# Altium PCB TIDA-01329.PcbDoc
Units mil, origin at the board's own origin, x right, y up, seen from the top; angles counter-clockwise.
Board outline 2100 x 1960 mil, 2 copper layers (Top Layer, Bottom Layer), stack 62 mil thick; 51 components, 43 nets, 188 pads, 34 vias.
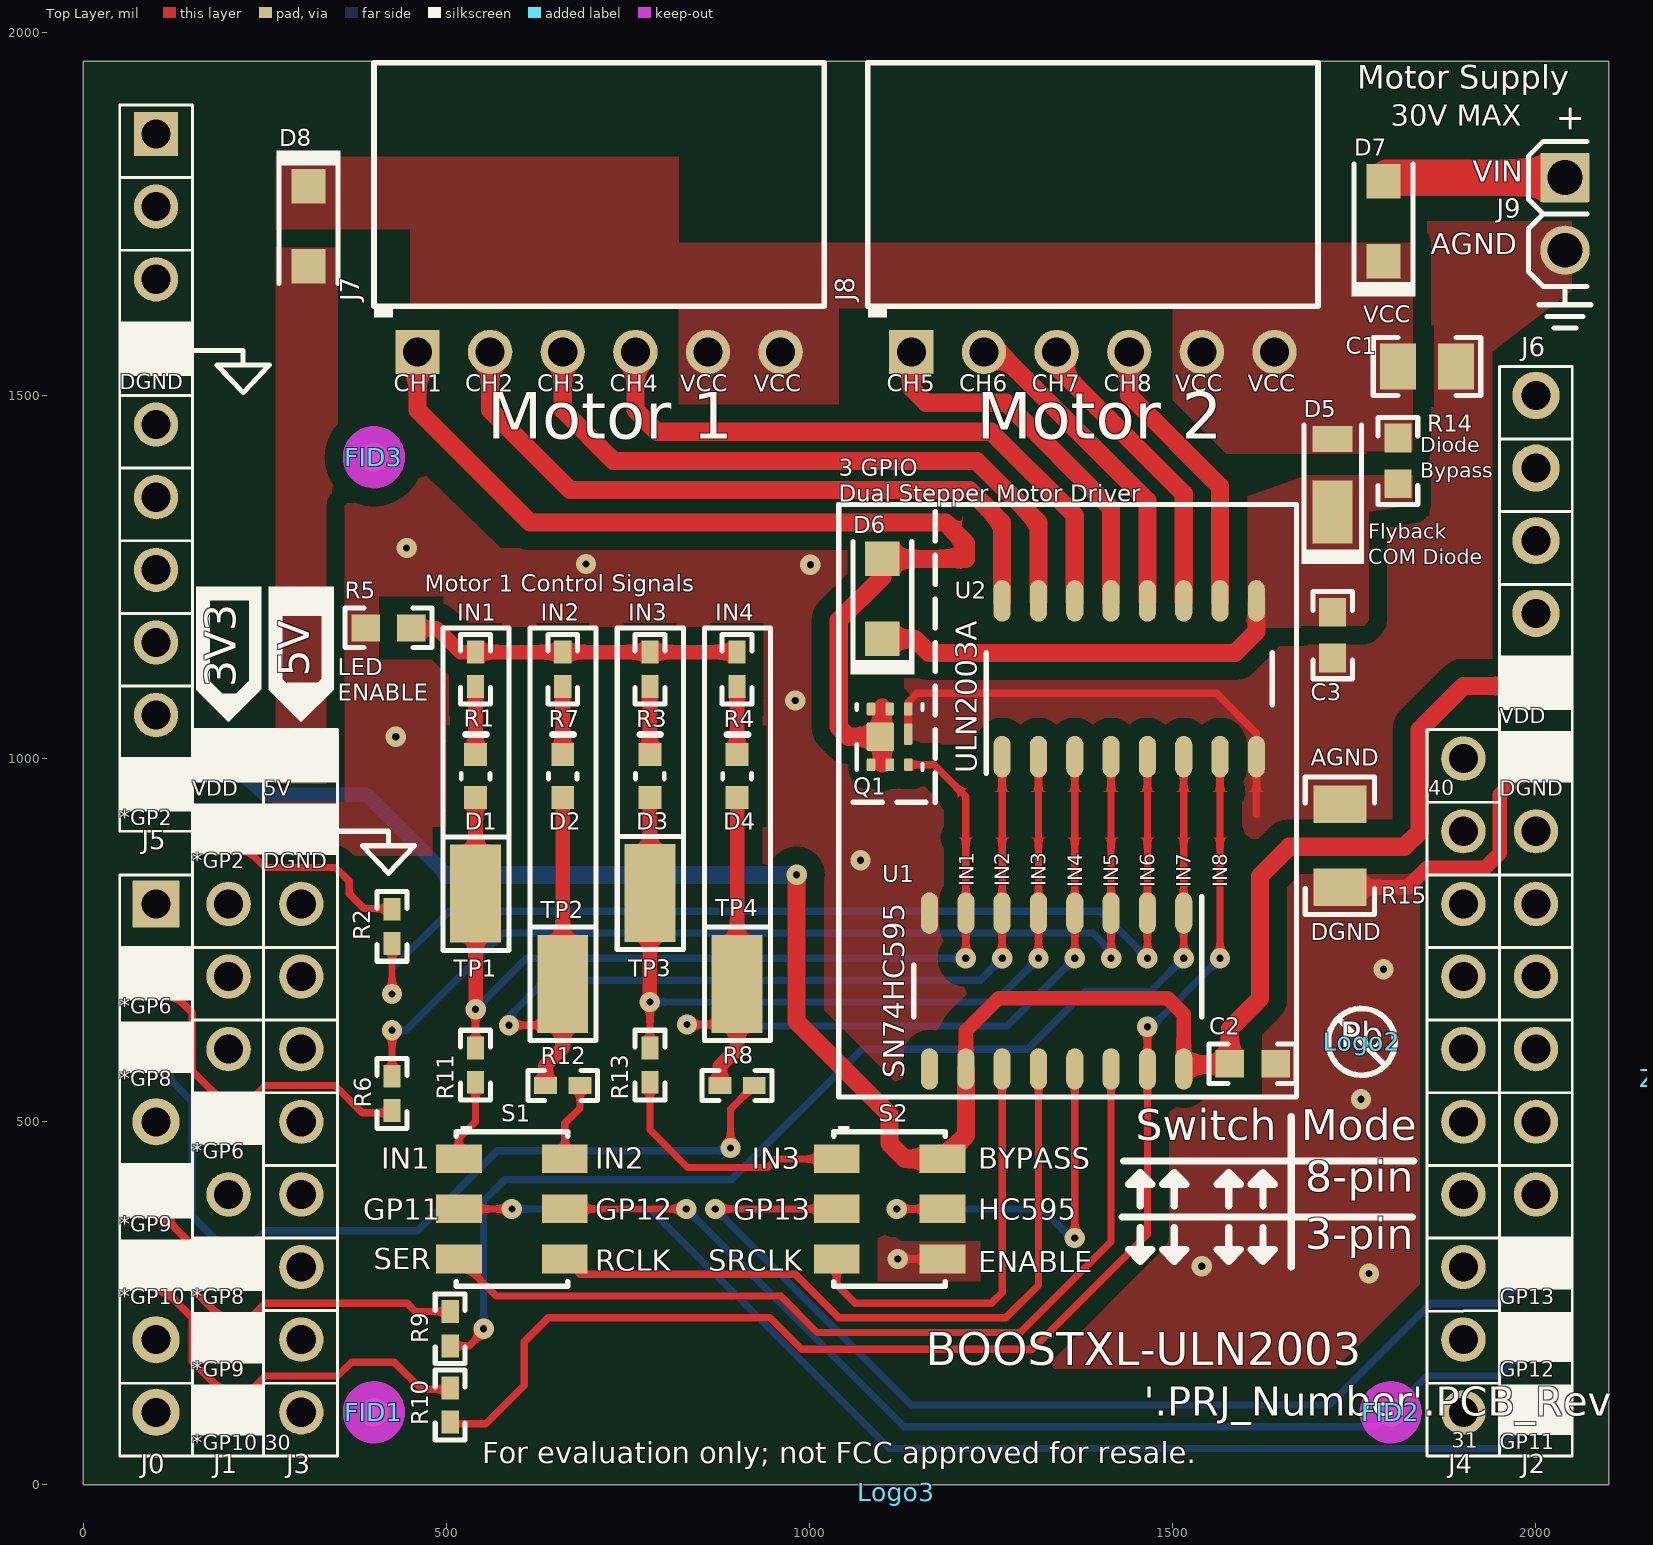
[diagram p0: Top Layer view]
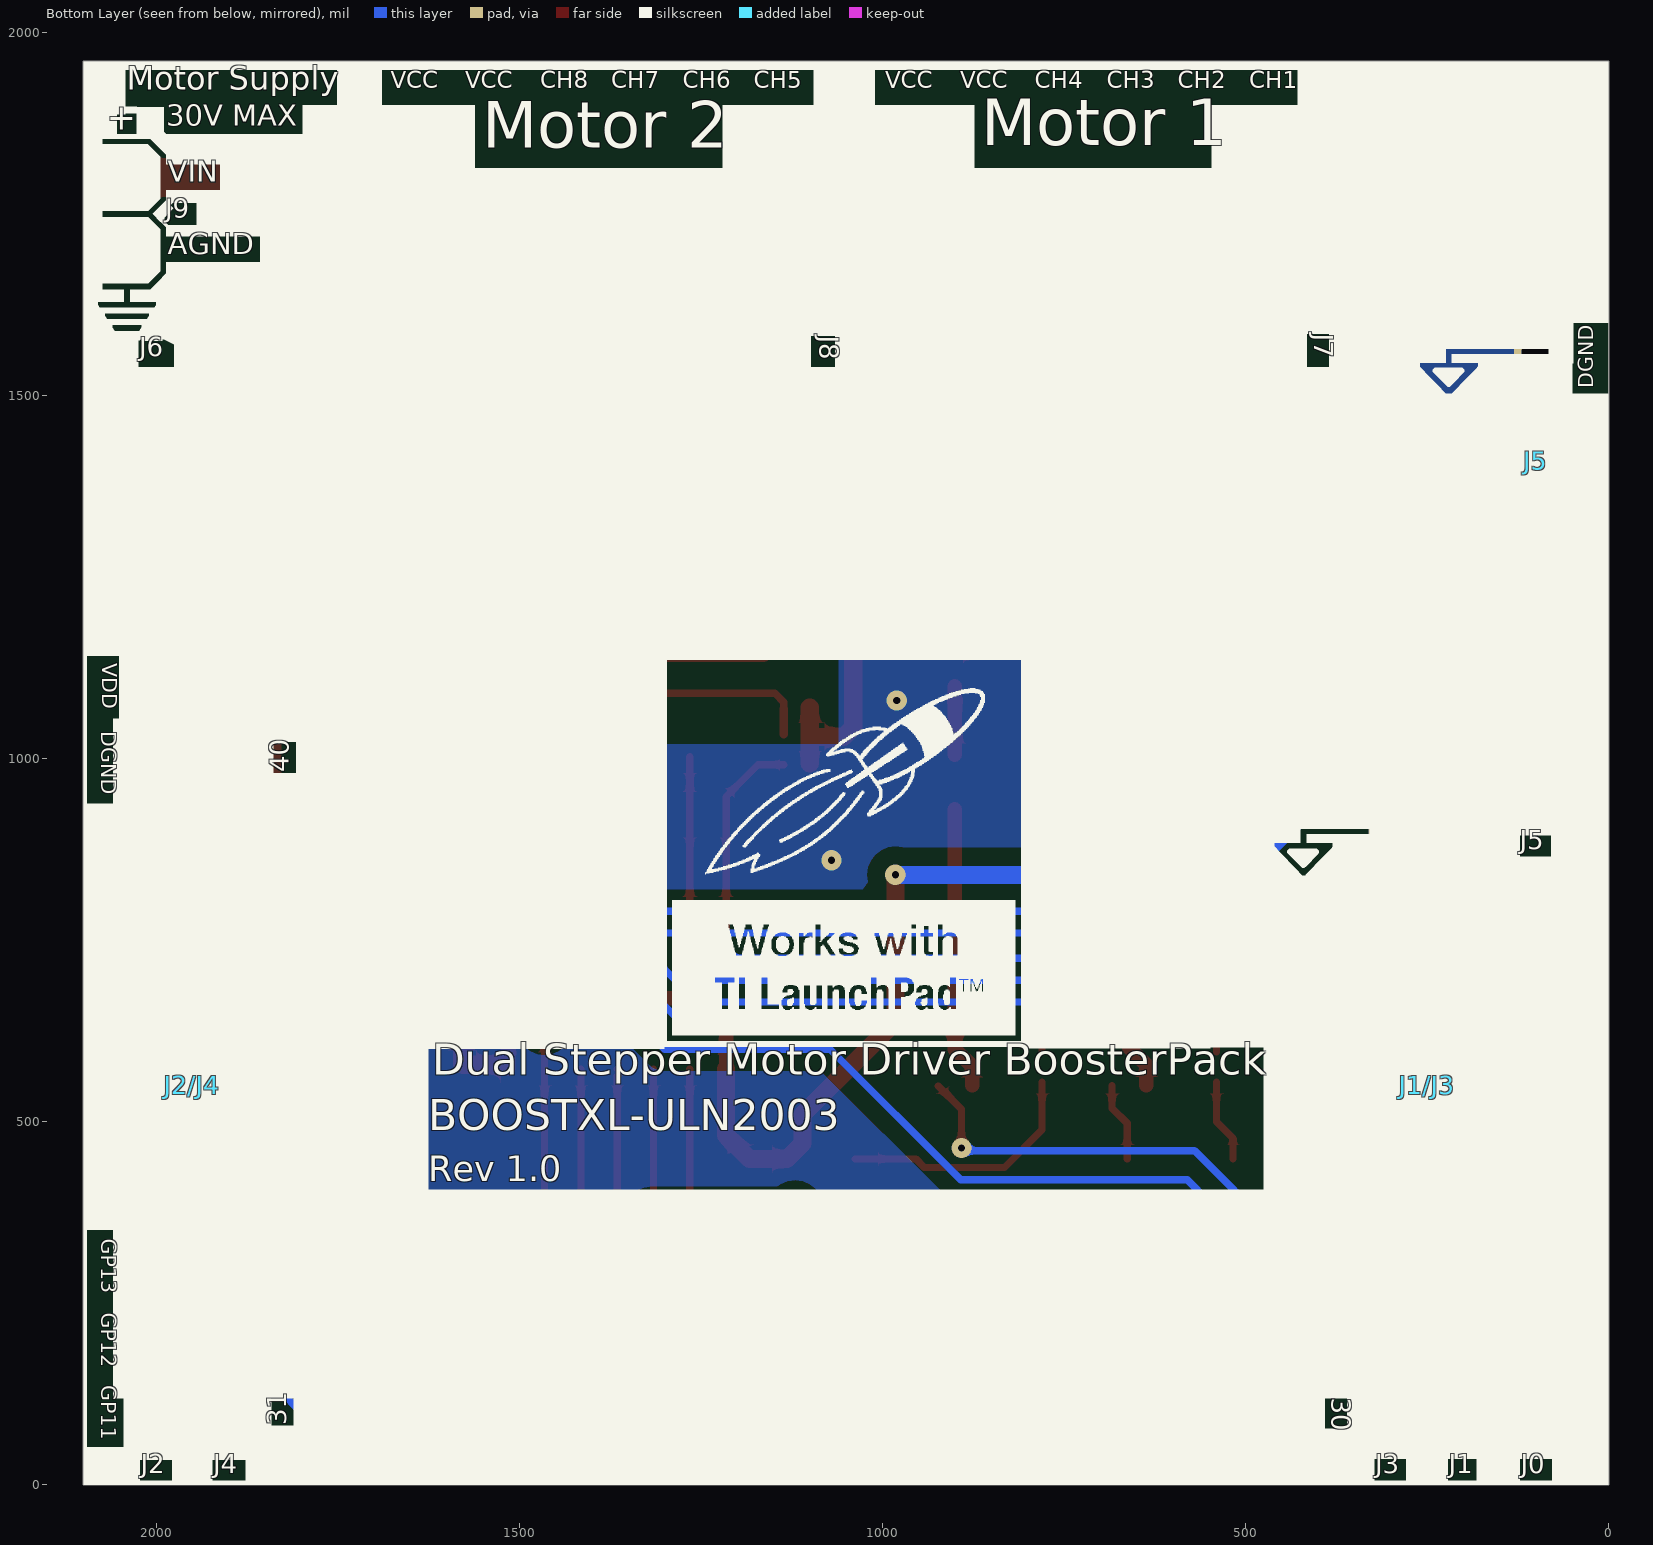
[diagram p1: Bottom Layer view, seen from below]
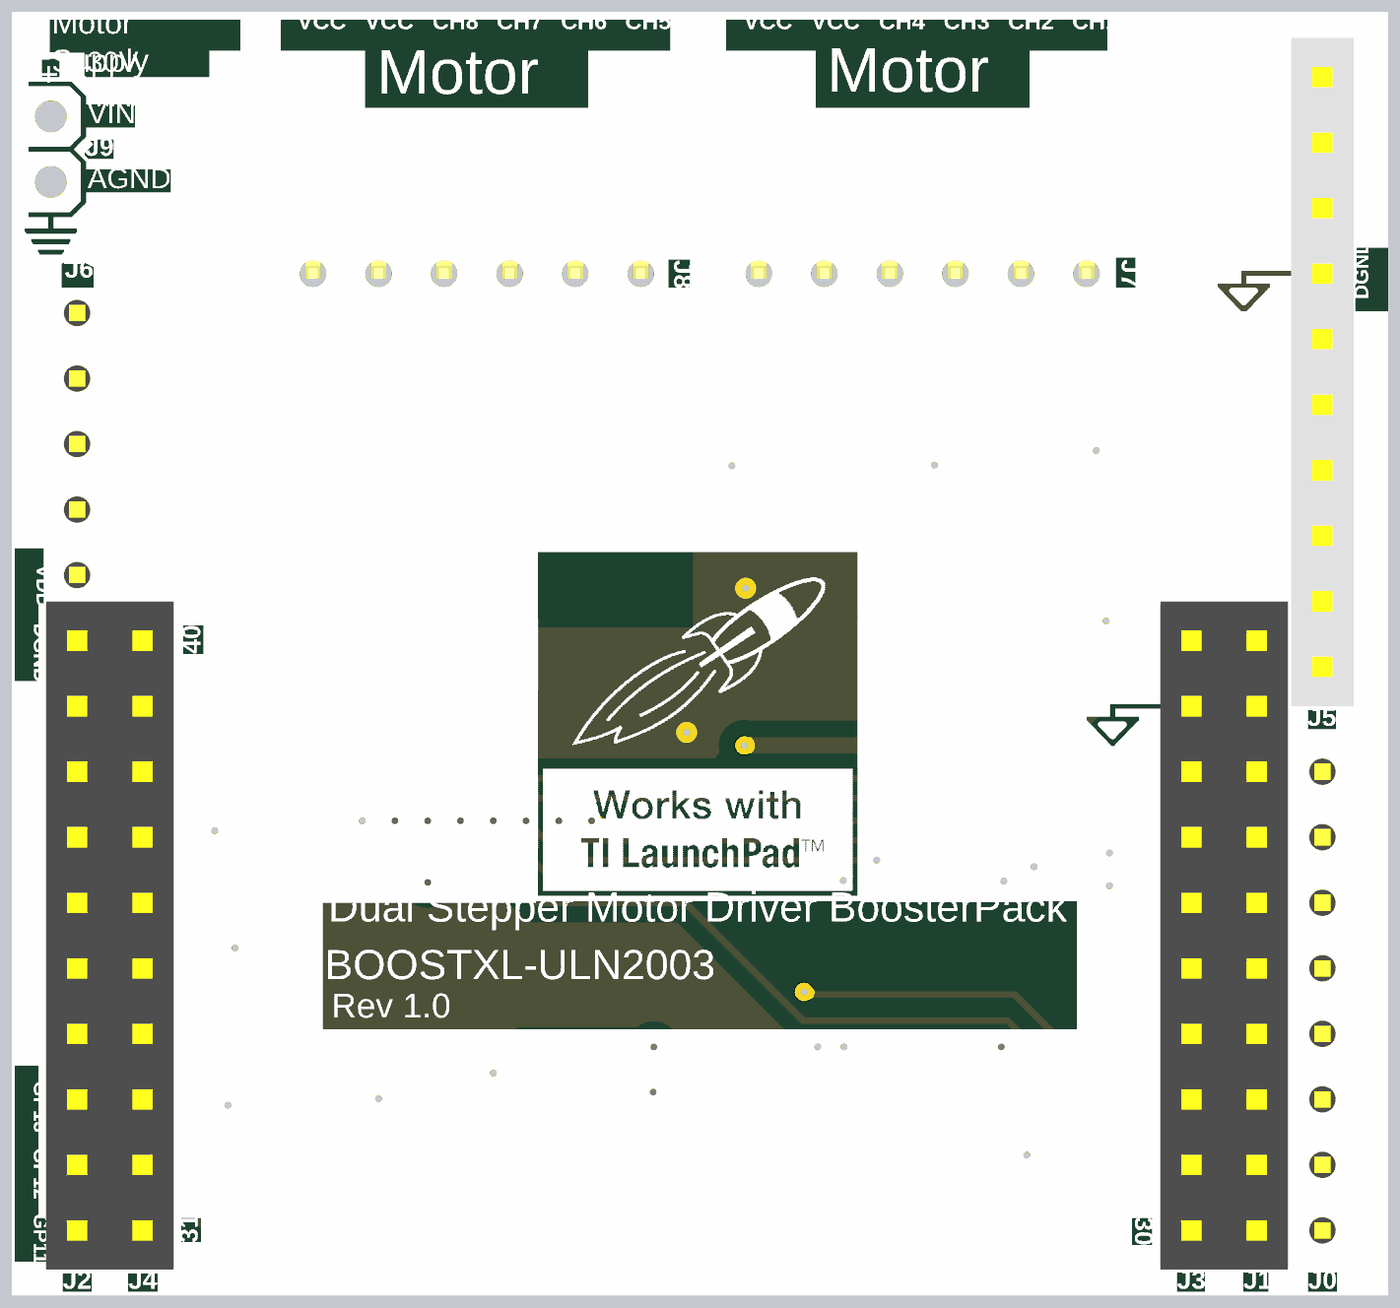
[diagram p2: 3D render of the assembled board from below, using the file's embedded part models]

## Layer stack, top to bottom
Top Solder: solder mask 0.4, Solder Resist, Dk 3.5
Top Layer: signal copper 1.4
Dielectric1: core 59.2, FR-4, Dk 4.8
Bottom Layer: signal copper 1.4
Bottom Solder: solder mask 0.4, Solder Resist, Dk 3.5

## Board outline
0,0 2100,0 2100,1960 0,1960

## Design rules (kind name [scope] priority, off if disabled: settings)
AcuteAngle [All] p1: minimum=4.50000000000000E+0001 checktracksonly=FALSE
AssemblyTestPointUsage [All] p1: valid=2
BoardOutlineClearance BoardOutlineClearance_MountingHoles [OnCopper and InComponentClass('Mounting Holes')] p1: gap=40
BoardOutlineClearance BoardOutlineClearance_Poly [OnCopper and InPoly] p2: gap=25
BoardOutlineClearance [OnCopper and Not InComponentClass('Logo') and not InComponentClass('FiducialMark') and not InRegion(1000,500,4000,800)] p3: gap=75 except(25: THPad-OutlineEdge; 35: Track-OutlineEdge; 50: Poly-OutlineEdge; 70: SMDPad-OutlineEdge)
Clearance Clearance_Keepouts [((IsTrack Or IsArc) And Not InPoly) And IsFree and IsKeepOut vs ((IsTrack Or IsArc) And Not InPoly) And IsFree and IsKeepOut] p1: gap=0
Clearance Clearance_Poly [InPolygon] p2: gap=25
Clearance [All] p3: gap=7.87
ComponentClearance J2toJ6Exception [InComponent('J2/J4') vs InComponent('J6')] p1: gap=5 collisioncheckmode=3 verticalgap=5 showdistances=FALSE
ComponentClearance J1toJ5Exception [InComponent('J1/J3') vs InComponent('J5')] p2: gap=5 collisioncheckmode=3 verticalgap=5 showdistances=FALSE
ComponentClearance ULN2803toULN2003Exception [InComponent('U2') vs InComponent('U3')] p3: gap=0 collisioncheckmode=3 verticalgap=0 showdistances=FALSE
ComponentClearance ComponentClearance_MountingHoles_FiducialMarks [InComponentClass('Mounting Holes') vs InComponentClass('FiducialMark')] p4: gap=50 collisioncheckmode=3 verticalgap=10 showdistances=FALSE
ComponentClearance ComponentClearance_Shunt [InComponentClass('Header') vs InComponentClass('Shunt')] p5: gap=0 collisioncheckmode=3 verticalgap=0 showdistances=FALSE
ComponentClearance ComponentClearance_Logo [InComponentClass('Logo')] p6: gap=5 collisioncheckmode=3 verticalgap=5 showdistances=FALSE
ComponentClearance ComponentClearance_ScrewToNut [(HasFootprint('NY PMS 440 0025 PH')) vs (HasFootprint('Keystone_1902C'))] p7: gap=5 collisioncheckmode=3 verticalgap=10 showdistances=FALSE
ComponentClearance ComponentClearance_MountingHoles [InComponentClass('Mounting Holes')] p8: gap=250 collisioncheckmode=3 verticalgap=100000 showdistances=FALSE
ComponentClearance ComponentClearance_SmallPassives [HasFootprint('0201*') or HasFootprint('0402*') or HasFootprint('0508') or HasFootprint('0603*') or HasFootprint('0612') or HasFootprint('0805*') or HasFootprint('0815*') or HasFootprint('0830*') or HasFootprint('1206*') or HasFootprint('1210*') or HasFootprint('1808*') or HasFootprint('1812*') or HasFootprint('1825*') or HasFootprint('2010*') or HasFootprint('2220*') or HasFootprint('2225*') or HasFootprint('2512*') or HasFootprint('2728*') or HasFootprint('3518*') vs HasFootprint('0201*') or HasFootprint('0402*') or HasFootprint('0508') or HasFootprint('0603*') or HasFootprint('0612') or HasFootprint('0805*') or HasFootprint('0815*') or HasFootprint('0830*') or HasFootprint('1206*') or HasFootprint('1210*') or HasFootprint('1808*') or HasFootprint('1812*') or HasFootprint('1825*') or HasFootprint('2010*') or HasFootprint('2220*') or HasFootprint('2225*') or HasFootprint('2512*') or HasFootprint('2728*') or HasFootprint('3518*')] p9: gap=14.96 collisioncheckmode=3 verticalgap=10 showdistances=FALSE
ComponentClearance ComponentClearance_THtoSMT [IsThruComponent vs IsSMTComponent] p10: gap=40 collisioncheckmode=3 verticalgap=30 showdistances=FALSE
ComponentClearance ComponentClearance_THtoTH [IsThruComponent vs IsThruComponent] p11: gap=30 collisioncheckmode=3 verticalgap=30 showdistances=FALSE
ComponentClearance [All] p12: gap=30 collisioncheckmode=3 verticalgap=10 showdistances=FALSE
DiffPairsRouting [All] p1: maxlimit=100 minlimit=10 mostfreqgap=10 toplayer_minwidth=15 toplayer_maxwidth=15 toplayer_prefwidth=15 bottomlayer_minwidth=15 bottomlayer_maxwidth=15 bottomlayer_prefwidth=15 maxuncoupledlength=1000
FabricationTestPointUsage TestPointUsage [All] p1: valid=2 allowmultiple=FALSE
FabricationTestpoint Testpoint [All] p1: side=3 testpointundercomponent=TRUE minsize=40 maxsize=100 preferedsize=60 minholesize=0 maxholesize=40 preferedholesize=32 testpointgrid=1 allowsidetop=TRUE allowsidebottom=TRUE usegrid=TRUE gridtolerance=0.01
FanoutControl Fanout_LCC [IsLCC] p1: bgadir=Out bgaviamode=Centered fanoutstyle=Auto fanoutdirection=Alternating viagrid=1 // Fanout_LCC (Default Rule)
FanoutControl Fanout_BGA [IsBGA] p2: bgadir=Out bgaviamode=Centered fanoutstyle=Auto fanoutdirection=Alternating viagrid=1 // Fanout_BGA (Default Rule)
FanoutControl Fanout_Default [All] p4: bgadir=Out bgaviamode=Centered fanoutstyle=Auto fanoutdirection=Alternating viagrid=1 // Fanout_Default (Default Rule)
FanoutControl Fanout_Small [(CompPinCount < 5)] p5: bgadir=Out bgaviamode=Centered fanoutstyle=Auto fanoutdirection=OutThenIn viagrid=1 // Fanout_Small (Default Rule)
HoleSize [All] p1: absolutevalues=TRUE maxlimit=251 minlimit=7.87 maxpercent=80.000 minpercent=20.000
MinimumAnnularRing MinimumAnnularRing_ThermalPadVias [IsVia and InAnyComponent] p1: minimumring=5.91
MinimumAnnularRing [All] p2: minimumring=8
MinimumSolderMaskSliver MinimumSolderMaskSliver_Logo [InComponentClass('Logo') vs InComponentClass('Logo')] p1: minsoldermaskwidth=0.7
MinimumSolderMaskSliver [All] p2: minsoldermaskwidth=3.94
PlaneConnect [All] p1: planeconnectstyle=Relief reliefexpansion=10 reliefentries=4 reliefconductorwidth=10 reliefairgap=10
PolygonConnect [All] p1: connectstyle=Direct reliefconductorwidth=10 reliefentries=4 polygonreliefangle="45 Angle" airgapwidth=10
RoutingVias ThermalPadVias [IsVia and InAnyComponent] p1: holewidth=7.87 width=19.68 viastyle="Through Hole" minholewidth=7.87 minwidth=19.68 maxholewidth=12.99 maxwidth=23.62
RoutingVias [All] p2: holewidth=16 width=34 viastyle="Through Hole" minholewidth=7.87 minwidth=26 maxholewidth=40 maxwidth=65
SilkToBoardRegionClearance [Not ((IsComment or IsDesignator) And (Hide <> 'False')) and not InRegion(1000,500,4000,800)] p1:
SilkToSilkClearance SilkToSilkClearance_Pb-FreeLogo [(HasFootprint('Pb-Free_Overlay_Medium') OR HasFootprint('Pb-Free_Overlay_Small')) vs (HasFootprint('Pb-Free_Overlay_Medium') OR HasFootprint('Pb-Free_Overlay_Small'))] p1: silktosilkclearance=0
SilkToSilkClearance [All] p2: silktosilkclearance=0
SilkToSolderMaskClearance SilkToComponentPadClearance [IsPad and InAnycomponent] p1: minsilkscreentomaskgap=0 clearancetoexposedcopper=TRUE
SilkToSolderMaskClearance "Silk to Solder Mask Opening" [All] p2: minsilkscreentomaskgap=0 clearancetoexposedcopper=FALSE
SolderMaskExpansion [All] p1: expansion=1.97
Width [All] p1: maxlimit=100 minlimit=6 preferedwidth=10 checkconnectedcopper=TRUE
15 further rules are at their usual default settings.

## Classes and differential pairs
component class Header: J0 J6 J9
component class TIDA-01329_Hardware: FID1 FID2 FID3 Logo2 Logo3 ZZ1 ZZ2 ZZ3
component class AssemblyNote: ZZ1 ZZ2 ZZ3
component class FiducialMark: FID1 FID2 FID3

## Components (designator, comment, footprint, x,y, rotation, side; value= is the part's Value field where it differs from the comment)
C1 "GRM21BR71H105KA12L" 0805_HV 1850,1540 r0 top
C2 "GRM188R71H104KA93D" 0603 1610,580 r0 top
C3 "GRM188R71H104KA93D" 0603 1720,1170 r270 top
D1 "LG L29K-G2J1-24-Z" "LG L29K_GREEN" 540,976 r90 top
D2 "LG L29K-G2J1-24-Z" "LG L29K_GREEN" 660,976 r90 top
D3 "LG L29K-G2J1-24-Z" "LG L29K_GREEN" 780,976 r90 top
D4 "LG L29K-G2J1-24-Z" "LG L29K_GREEN" 900,976 r90 top
D5 "DFLZ12-7" powerDI123 1720,1390 r90 top
D6 "DB2W40200L" SOD-123F 1100,1220 r90 top
D7 "DB2W40200L" SOD-123F 1790,1740 r90 top
D8 "DB2W40200L" SOD-123F 310,1733 r270 top
FID1 "Fiducial" Fiducial10-20 400,100 r0 top
FID2 "Fiducial" Fiducial10-20 1800,100 r0 top
FID3 "Fiducial" Fiducial10-20 400,1415 r0 top
J0 "TSW-108-07-G-S" TSW-108-07-G-S 100,450 r270 top
J1/J3 "SSQ-110-03-T-D" BoosterPack_40pin_J1J3 250,550 r180 bottom
J2/J4 "SSQ-110-03-T-D" BoosterPack_40pin_J2J4 1950,550 r180 bottom
J5 "SSQ-110-03-F-S" Samtec_SSQ-110-03-x-S 100,1410 r270 bottom
J6 "TSW-105-07-G-S" TSW-105-07-G-S 2000,1300 r90 top
J7 "PPPC061LGBN-RC" Sullins_xPxC061LGBN 710,1560 r90 top
J8 "PPPC061LGBN-RC" Sullins_xPxC061LGBN 1390,1560 r90 top
J9 "PEC02SAAN" CONN_PEC02SAAN 2040,1750 r270 top
Logo2 "Pb-Free Symbol" Pb-Free_Overlay_Small 1760,610 r0 top
Logo3 "FCC disclaimer" FCC_disclaimer 1119,-10 r0 top
Q1 "CSD17571Q2" TRANS_NexFET_Q2 1110,1030 r90 top
R1 "CRCW04021K00JNED" 0402 540,1123 r270 top
R2 "CRCW0402560RJNED" 0402 425,769 r90 top
R3 "CRCW04021K00JNED" 0402 780,1123 r270 top
R4 "CRCW04021K00JNED" 0402 900,1123 r270 top
R5 "ERJ-3GEY0R00V" 0603 420,1180 r0 top
R6 "CRCW0402560RJNED" 0402 425,539 r270 top
R7 "CRCW04021K00JNED" 0402 660,1123 r270 top
R8 "CRCW0402560RJNED" 0402 900,550 r0 top
R9 "CRCW0402560RJNED" 0402 505,215 r90 top
R10 "CRCW0402560RJNED" 0402 505,110 r90 top
R11 "CRCW0402560RJNED" 0402 540,578 r90 top
R12 "CRCW0402560RJNED" 0402 660,550 r180 top
R13 "CRCW0402560RJNED" 0402 780,578 r90 top
R14 "ERJ-3GEY0R00V" 0603 1810,1410 r90 top
R15 "ERJ-8GEY0R00V" 1206 1730,880 r270 top
S1 "CAS-D20TA" SW_CAS-D20TA 590,380 r0 top
S2 "CAS-D20TA" SW_CAS-D20TA 1110,380 r0 top
TP1 "5015" Testpoint_Keystone_Miniature 540,814 r90 top
TP2 "5015" Testpoint_Keystone_Miniature 660,690 r90 top
TP3 "5015" Testpoint_Keystone_Miniature 780,815 r90 top
TP4 "5015" Testpoint_Keystone_Miniature 900,690 r90 top
U1 "SN74HC595DR" D0016A_N 1340,680 r270 top
U2 "ULN2003ADR" D0016A_N 1440,1110 r90 top
ZZ1 "These assemblies are ESD sensitive, ESD precautions shall be observed." AssemblyNote 2532,1787 r90 top
ZZ2 "These assemblies must be clean and free from flux and all contaminants. Use of no clean flux is not acceptable." AssemblyNote 2355,234 r90 top
ZZ3 "These assemblies must comply with workmanship standards IPC-A-610 Class 2, unless otherwise specified." AssemblyNote 2177,560 r90 top

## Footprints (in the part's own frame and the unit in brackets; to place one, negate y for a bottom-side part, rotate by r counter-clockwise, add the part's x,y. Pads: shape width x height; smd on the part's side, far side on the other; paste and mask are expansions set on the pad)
0402 [mm] "0402 from SM-752 data"
  rect 0.8x0.6 smd: 1(-0.6,0) 2(0.6,0)
  silkscreen extent -1.22,-0.52 1.22,0.52, body extent -0.55,-0.3 0.55,0.3, height 0.6
0603 [mm] "0603 from SM-752 data"
  rect 1x0.95 smd: 1(-0.8,0) 2(0.8,0)
  silkscreen extent -1.52,-0.69 1.52,0.69, body extent -0.87,-0.47 0.87,0.47, height 1
0805_HV [mil] "0805 with 30mil clearance between pads"
  rect 50x63 smd: 1(-40,0) 2(40,0)
  silkscreen extent -74,-40 74,40, body extent -43,-29 43,29, height 57
1206 [mm] "1206 from SM-752 data"
  rect 1.3x1.85 smd: 1(-1.45,0) 2(1.45,0)
  silkscreen extent -2.4,-1.21 2.4,1.21, body extent -1.7,-0.9 1.7,0.9, height 1.35
AssemblyNote [mil] "Assembly Note"
BoosterPack_40pin_J1J3 [mm] "Receptacle, 2.54mm, 10x2, TH"
  rrect6% 1.55x1.55 hole 1.02 mask+0.025: 1(1.27,11.43)
  round 1.55 hole 1.02 mask+0.025: 2(1.27,8.89) 3(1.27,6.35) 4(1.27,3.81) 5(1.27,1.27) 6(1.27,-1.27) 7(1.27,-3.81) 8(1.27,-6.35) 9(1.27,-8.89) 10(1.27,-11.43) 21(-1.27,11.43) 22(-1.27,8.89) 23(-1.27,6.35) 24(-1.27,3.81) 25(-1.27,1.27) 26(-1.27,-1.27) 27(-1.27,-3.81) 28(-1.27,-6.35) 29(-1.27,-8.89) 30(-1.27,-11.43)
  body extent -2.48,-12.95 2.48,12.95, height 8.51
BoosterPack_40pin_J2J4 [mm] "Receptacle, 2.54mm, 10x2, TH"
  round 1.55 hole 1.02 mask+0.025: 11(-1.27,-11.43) 12(-1.27,-8.89) 13(-1.27,-6.35) 14(-1.27,-3.81) 15(-1.27,-1.27) 16(-1.27,1.27) 17(-1.27,3.81) 18(-1.27,6.35) 19(-1.27,8.89) 20(-1.27,11.43) 31(1.27,-11.43) 32(1.27,-8.89) 33(1.27,-6.35) 34(1.27,-3.81) 35(1.27,-1.27) 36(1.27,1.27) 37(1.27,3.81) 38(1.27,6.35) 39(1.27,8.89) 40(1.27,11.43)
  body extent -2.48,-12.95 2.48,12.95, height 8.51
CONN_PEC02SAAN [mil] "SULLINS"
  rrect7% 68x68 hole 48: 1(-50,0)
  round 68 hole 48: 2(50,0)
  body extent -100,-50 100,50, height 330
D0016A_N [mm] "SOIC, 16-Leads, Body 9.9x3.9mm, Pitch 1.27mm, IPC Medium Density"
  oval 1.45x0.6 smd: 1(-2.725,4.445) 2(-2.725,3.175) 3(-2.725,1.905) 4(-2.725,0.635) 5(-2.725,-0.635) 6(-2.725,-1.905) 7(-2.725,-3.175) 8(-2.725,-4.445) 9(2.725,-4.445) 10(2.725,-3.175) 11(2.725,-1.905) 12(2.725,-0.635) 13(2.725,0.635) 14(2.725,1.905) 15(2.725,3.175) 16(2.725,4.445)
  silkscreen extent -3.3,-5 0.9,5.08, body extent -3,-4.95 3,4.95, height 1.6
FCC_disclaimer [mil]
Fiducial10-20 [mm]
  round 1 smd mask+0.5: 1(0,0)
  Top Layer keep-out circle w1.178: c0,0 r0.5
"LG L29K_GREEN" [mm] "OSRAM"
  rect 0.8x0.8 smd paste-0.4: 1(-0.75,0) 2(0.75,0)
  silkscreen extent -0.1,-0.5 1.45,0.5, body extent -0.9,-0.45 0.9,0.45, height 0.67
Pb-Free_Overlay_Small [mil]
  silkscreen extent -46,-46 46,46
powerDI123 [mm] "Diodes Inc recommended land pattern, document number DS30628 Rev. 6-2"
  rect 2.2x1.4 smd: 1(-1.275,0)
  rect 0.9x1.4 smd: 2(1.275,0)
  silkscreen extent -3.1,-1.09 1.76,1.09, body extent -2.38,-0.97 1.52,0.96, height 1
Samtec_SSQ-110-03-x-S [mm] "Receptacle, 2.54mm, 10x1, TH"
  rect 1.55x1.55 hole 1.02 mask+0.025: 1(-11.43,0)
  round 1.55 hole 1.02 mask+0.025: 2(-8.89,0) 3(-6.35,0) 4(-3.81,0) 5(-1.27,0) 6(1.27,0) 7(3.81,0) 8(6.35,0) 9(8.89,0) 10(11.43,0)
  body extent -12.95,-1.21 12.95,1.21, height 8.51
SOD-123F [mm] "NXP recommended land pattern"
  rect 1.2x1.2 smd paste-0.05: 1(-1.4,0) 2(1.4,0)
  silkscreen extent -2.64,-1.12 2.01,1.12, body extent -1.8,-0.85 1.8,0.85, height 1.2
Sullins_xPxC061LGBN [mm] "Receptacle, 2.54mm, 6x1, R/A, TH"
  rect 1.55x1.55 hole 1.02 mask+0.025: 1(0,6.35)
  round 1.55 hole 1.02 mask+0.025: 2(0,3.81) 3(0,1.27) 4(0,-1.27) 5(0,-3.81) 6(0,-6.35)
  silkscreen extent 1.21,-7.87 10.11,7.87, body extent -0.2,-7.87 10.11,7.87, height 2.54
SW_CAS-D20TA [mm] "SMD, 6-Leads, Body 5.4x3.9mm, Pitch 1.75mm"
  rect 1.6x1 smd: 1(-1.85,1.75) 2(-1.85,0) 3(-1.85,-1.75) 4(1.85,1.75) 5(1.85,0) 6(1.85,-1.75)
  silkscreen extent -1.95,-2.7 1.95,2.9, body extent -2.1,-2.7 2.1,2.7, height 2.5
Testpoint_Keystone_Miniature [mil] "Miniature SMT test point"
  rect 135x70 smd: 1(0,0)
  silkscreen extent -78,-46 78,45, body extent -52,-20 52,20, height 61
TRANS_NexFET_Q2 [mm] "TI recommended land pattern M0167-01"
  rrect33% 0.45x0.3 smd: 1(-0.975,0.65) 2(-0.975,0) 3(-0.975,-0.65) 4(0.975,-0.65) 5(0.975,0) 6(0.975,0.65)
  rrect33% 0.75x0.3 smd paste-0.025: 7(0.095,-0.65)
  rrect11% 1x0.95 smd paste-0.025: 8(0,0.325)
  silkscreen extent -1.15,-1.15 1.15,1.15, body extent -1,-1 1,1, height 0.85
TSW-105-07-G-S [mm] "Samtec 100mil, 1x5, 230 mil above insulator"
  rrect6% 1.65x1.65 hole 1.016: 1(-5.08,0)
  round 1.65 hole 1.016: 2(-2.54,0) 3(0,0) 4(2.54,0) 5(5.08,0)
  silkscreen extent -6.1,-1.27 6.1,1.27, body extent -6.35,-1.27 6.35,1.27, height 8.38
TSW-108-07-G-S [mm] "Samtec 100mil, 1x8, 230 mil above insulator"
  rrect6% 1.65x1.65 hole 1.016: 1(-8.89,0)
  round 1.65 hole 1.016: 2(-6.35,0) 3(-3.81,0) 4(-1.27,0) 5(1.27,0) 6(3.81,0) 7(6.35,0) 8(8.89,0)
  body extent -10.16,-1.27 10.16,1.27, height 8.38

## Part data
C1: "CAP, CERM, 1 µF, 50 V, +/- 10%, X7R, 0805"
C2 C3: "CAP, CERM, 0.1 µF, 50 V, +/- 10%, X7R, 0603"
D1 D2 D3 D4: "LED, Green, SMD"
D5: "Diode, Zener, 12 V, 1 W, PowerDI123"
D6 D7 D8: "Diode, Schottky, 40 V, 2 A, SOD-123F"
FID1 FID2 FID3: "Fiducial mark.  There is nothing to buy or mount."
J0: "Header, 100mil, 8x1, Gold, TH"
J1/J3: library part BoosterPack_40pin_J1J3, "Receptacle, 2.54mm, 10x2, Tin, TH"
J2/J4: library part BoosterPack_40pin_J2J4, "Receptacle, 2.54mm, 10x2, Tin, TH"
J5: "Receptacle, 2.54mm, 10x1, Gold, TH"
J6: "Header, 100mil, 5x1, Gold, TH"
J7 J8: "Receptacle, 2.54mm, 6x1, Gold, R/A, Black, TH"
J9: "Header, 100mil, 2x1, Tin, TH"
Logo2: library part Pb-Free
Logo3: library part FCC_disclaimer, "FCC_disclaimer"
Q1: "MOSFET, N-CH, 30 V, 7.6 A, SON 2x2mm"
R1 R3 R4 R7: "RES, 1.0 k, 5%, 0.063 W, 0402"
R2 R6 R8 R9 R10 R11 R12 R13: "RES, 560, 5%, 0.063 W, 0402"
R5 R14: "RES, 0, 5%, 0.1 W, 0603"
R15: "RES, 0, 5%, 0.25 W, 1206"
S1 S2: "Switch, Dual SPDT,  2 Pos, 0.1A, 6VDC, SMD"
TP1 TP2 TP3 TP4: "Test Point, Miniature, SMT"
U1: "8-Bit Shift Registers With 3-State Output Register, D0016A"
U2: "7-Channel Relay and Inductive Load Sink Driver, D0016A"
ZZ1 ZZ2 ZZ3: library part AssemblyNote

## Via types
v1: diameter 28, hole 10, Top Layer to Bottom Layer, 34 vias

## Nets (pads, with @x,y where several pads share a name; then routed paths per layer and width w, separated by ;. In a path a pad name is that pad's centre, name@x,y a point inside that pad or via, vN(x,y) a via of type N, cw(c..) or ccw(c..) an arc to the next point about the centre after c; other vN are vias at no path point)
3V3: C2.1 J1/J3.1 J6.1 S2.4 U1.10 U1.16 | length 2857.9
  Top Layer w10: U1.16 U1.16@1520.79,578.5
  Top Layer w20: U1.10 1215,625 1260,670 1493,670 1515,648 U1.16
  Top Layer w25: v1(982,840) 982,638 1110,510 1110,470 1131.1,448.9 S2.4 1215,481.06 U1.10 ; U1.16@1520.79,578.5 1577.01,578.5 C2.1 1578.5,628.5 1620,670 1620,838.62 1660,878.62 1818.62,878.62 1840,900 1840,1040 1900,1100 J6.1
  Bottom Layer w20: J1/J3.1 250,950 390,950 500,840
  Bottom Layer w25: 500,840 v1(982,840)
5V: D8.2 J1/J3.21
AGND: C1.2 C3.2 J9.2 Q1.4 Q1.7 R15.1 U2.8 | length 663.3
  Top Layer w10: Q1.4 1135.59,1077.71 1147.88,1090 1560,1090 1615,1035 U2.8 1615,922.99
  Top Layer w12: Q1.7 Q1.4
COM: C3.1 D5.1 D6.1 R14.1 U2.9 | length 577.5
  Top Layer w25: D6.1 1145.12,1164.88 1164.47,1145.53 1585.53,1145.53 1615,1175 U2.9
DGND: C2.2 J1/J3.22 J2/J4.20 J5.4 R5.1 R15.2 S2.6 U1.8 | length 461.9
  Top Layer w10: v1(1121.1,311.1) S2.6
  Top Layer w20: J1/J3.22 J1/J3.22@310,900 ; R15.2 1822.91,822.91 1850,850 1930,850 1950,870 1950,950 J2/J4.20
  other v1: 1770,291 1540,301 1759,531 1790,710 1070,860 430,1030 980,1080 1001,1267 692,1268 445,1290
GP2: J1/J3.2 J5.10 R2.2 | length 403.9
  Top Layer w10: J5.10 122.5,960 182.5,900 J1/J3.2 250,850 347,850 366,831 366,814 386.5,793.5 R2.2@425,793.5
GP6: J0.2 J1/J3.6 R6.2 | length 502.7
  Top Layer w10: J0.2 150,650 150,570 200,520 J1/J3.6 250,550 346.38,550 383.87,512.5 R6.2@425,512.5
GP8: J0.3 J1/J3.8 R8.2 | length 1189
  Top Layer w10: v1(891,464) 891,517.38 R8.2@923,549.38
  Bottom Layer w10: J0.3@100,590 100,578 150,528 150,370 200,320 J1/J3.8 250,350 460,350 570,460 883,460 887,464 v1(891,464)
GP9: J0.5 J1/J3.9 R9.2 | length 551.8
  Top Layer w10: J0.5@100,380 150,330 150,270 200,220 J1/J3.9 250,250 446,250 457.38,238.62 R9.2
GP10: J0.6 J1/J3.10 R10.2 | length 556.3
  Top Layer w10: J0.6@110,270 150,230 150,170 200,120 J1/J3.10 250,150 350,150 369,169 428,169 465.38,131.62 R10.2@505,131.62
GP11: J2/J4.11 S1.2 | length 1640.2
  Top Layer w10: S1.2 v1(590,380)
  Bottom Layer w10: v1(590,380) 780,380 1110,50 1950,50 J2/J4.11
GP12: J2/J4.12 S1.5 | length 1511.1
  Top Layer w10: S1.5 v1(830,380)
  Bottom Layer w10: v1(830,380) 1130,80 1780,80 1850,150 1950,150 J2/J4.12
GP13: J2/J4.13 S2.2 | length 1487.7
  Top Layer w10: v1(870,380) S2.2
  Bottom Layer w10: v1(870,380) 1140,110 1715.38,110 1855.38,250 1950,250 J2/J4.13
IN1: D1.1 Q1.3 R11.2 TP1.1 U1.7 | length 1374.4
  Top Layer w10: R11.2@540,596.5 v1(540,655) ; Q1.3 1171.26,991.61 1215,947.87 1215,922.99 U1.7 v1(1215,725)
  Top Layer w20: v1(540,655) 540,800 D1.1
  Bottom Layer w10: v1(540,655) 561,676 610,725 v1(1215,725)
IN2: D2.1 R12.2 TP2.1 U1.6 U2.1 | length 1465.1
  Top Layer w10: v1(586,633) TP2.1@659,633 ; v1(1265,725) U1.6 1265,922.99 U2.1
  Top Layer w20: R12.2 636.38,578.38 660,602 TP2.1 660,930.47
  Bottom Layer w10: v1(586,633) 586,645 636,695 1235,695 v1(1265,725)
IN3: D3.1 R13.2 TP3.1 U1.5 U2.2 | length 1171.5
  Top Layer w10: R13.2@780,596.5 R13.2 v1(780,665) ; v1(1315,725) U1.5 1315,922.99 U2.2
  Top Layer w20: v1(780,665) TP3.1 780,930.47
  Bottom Layer w10: v1(780,665) 1255,665 v1(1315,725)
IN4: D4.1 R8.1 TP4.1 U1.4 U2.3 | length 1308.5
  Top Layer w10: v1(831,634) TP4.1@899,634 ; v1(1365,725) U1.4 1365,922.99 U2.3
  Top Layer w20: R8.1 876.38,576.38 900,600 TP4.1 900,930.47
  Bottom Layer w10: v1@831,632 1272,632 v1(1365,725)
IN5: R6.1 U1.3 U2.4 | length 1407
  Top Layer w10: R6.1 v1(425,626) ; v1(1415,725) U1.3 1415,922.99 U2.4
  Bottom Layer w10: v1(425,626) 444,626 449,631 578,760 1390,760 1415,735 v1(1415,725)
IN6: R2.1 U1.2 U2.5 | length 1481.7
  Top Layer w10: v1(425,676) R2.1 ; v1(1465,725) U1.2 1465,922.99 U2.5
  Bottom Layer w10: v1(425,676) 425,711 504,790 1400,790 v1(1465,725)
IN7: R9.1 U1.1 U2.6 | length 1617.3
  Top Layer w10: R9.1 531.38,191.38 v1@556,216 ; v1(1515,725) U1.1 1515,922.99 U2.6
  Bottom Layer w10: v1(551,215) 551,391 580,420 892,420 1072,600 1300,600 1380,680 1470,680 v1(1515,725)
IN8: R10.1 U1.15 U2.7 | length 1850
  Top Layer w10: R10.1@505,84.38 554.38,84.38 607,137 607,197 640,230 945.43,230 988.59,186.84 1306.84,186.84 1465,345 v1(1465,631) ; v1(1565,725) 1565,922.99 U2.7
  Bottom Layer w10: v1(1465,631) 1465,625 v1(1565,725)
M1_CH1: D6.2 J7.1 Q1.1 Q1.2 Q1.5 Q1.6 Q1.8 | length 1443.3
  Top Layer w25: J7.1 460,1480 615,1325 1187.01,1325 1215,1297.01 1215,1275 D6.2@1100.53,1275 ; Q1.8 1053.55,1030 1040,1043.55 1040,1190 1100,1250 D6.2 ; 1100,993.23 1100,1070
M1_CH2: J7.2 U2.16 | length 956.9
  Top Layer w25: J7.2 560,1480 670,1370 1220,1370 1265,1325 1265,1297.01 U2.16
M1_CH3: J7.3 U2.15 | length 906.9
  Top Layer w25: J7.3 660,1480 730,1410 1230,1410 1315,1325 1315,1297.01 U2.15
M1_CH4: J7.4 U2.14 | length 862.8
  Top Layer w25: J7.4 760,1480 790,1450 1250,1450 1365,1335 1365,1297.01 U2.14
M2_CH5: J8.1 U2.13 | length 521.1
  Top Layer w25: J8.1 1140,1510 1160,1490 1270,1490 1415,1345 1415,1297.01 U2.13
M2_CH6: J8.2 U2.12 | length 447.6
  Top Layer w25: J8.2 1260,1560 1465,1355 1465,1297.01 U2.12
M2_CH7: J8.3 U2.11 | length 415.2
  Top Layer w25: J8.3 1340,1540 1515,1365 1515,1297.01 U2.11
M2_CH8: J8.4 U2.10 | length 394.5
  Top Layer w25: J8.4 1440,1500 1565,1375 1565,1297.01 U2.10
NetD1_2: D1.2 R1.2 | length 93.9
  Top Layer w20: D1.2 R1.2
NetD2_2: D2.2 R7.2 | length 93.9
  Top Layer w20: D2.2 R7.2
NetD3_2: D3.2 R3.2 | length 93.9
  Top Layer w20: D3.2 R3.2
NetD4_2: D4.2 R4.2 | length 93.9
  Top Layer w20: D4.2 R4.2
NetR1_1: R1.1 R3.1 R4.1 R5.2 R7.1 | length 460.9
  Top Layer w20: R5.2@452.5,1179 487,1179 519.38,1146.62 R1.1 R7.1 R3.1 R4.1
NetR11_1: R11.1 S1.1 | length 114.9
  Top Layer w10: S1.1 517.17,477.17 540,500 R11.1
NetR12_1: R12.1 S1.4 | length 109.7
  Top Layer w10: S1.4 662.83,497.83 683.62,518.62 R12.1
NetR13_1: R13.1 S2.1 | length 348.9
  Top Layer w10: R13.1 780,489 831.87,437.13 942.13,437.13 953.9,448.9 S2.1
OE: S2.5 U1.13 | length 561.3
  Top Layer w10: v1(1120,380) S2.5 ; v1(1365,340) 1365,562.72 1360,567.72 U1.13
  Bottom Layer w10: v1(1120,380) 1320,380 1360,340 v1(1365,340)
RCLK: S1.6 U1.12 | length 1002.1
  Top Layer w10: S1.6 683.94,290 980,290 1040,230 1270,230 1315,275 U1.12
SER: S1.3 U1.14 | length 1229.2
  Top Layer w10: S1.3 568.27,260 960,260 1010,210 1290,210 1415,335 U1.14
SRCLK: S2.3 U1.11 | length 587.8
  Top Layer w10: S2.3 1037.17,275.67 1062.83,250 1250,250 1265,265 U1.11
VCC: C1.1 D5.2 D7.1 D8.1 J7.5 J7.6 J8.5 J8.6 R14.2
VIN: D7.2 J9.1 | length 245.1
  Top Layer w50: D7.2@1794.88,1800 J9.1
pads on no net: FID1.1 FID2.1 FID3.1 J0.1 J0.4 J0.7 J0.8 J1/J3.3 J1/J3.4 J1/J3.5 J1/J3.7 J1/J3.23 J1/J3.24 J1/J3.25 J1/J3.26 J1/J3.27 J1/J3.28 J1/J3.29 J1/J3.30 J2/J4.14 J2/J4.15 J2/J4.16 J2/J4.17 J2/J4.18 J2/J4.19 J2/J4.31 J2/J4.32 J2/J4.33 J2/J4.34 J2/J4.35 J2/J4.36 J2/J4.37 J2/J4.38 J2/J4.39 J2/J4.40 J5.1 J5.2 J5.3 J5.5 J5.6 J5.7 J5.8 J5.9 J6.2 J6.3 J6.4 J6.5 U1.9

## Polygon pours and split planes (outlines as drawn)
VCC on Top Layer "TOP_LAYER_VCC_P008" (solid, remove dead copper, pour order 8): 820,1710 820,1829 265,1829 265,1729 450,1729 450,1620 820,1620 820,1480 1040,1480 1040,1620 1500,1620 1500,1480 1560,1420 1830,1420 1830,1710
COM on Top Layer "TOP_LAYER_COM_P004" (solid, remove dead copper, pour order 4): 1600,1360 1600,1180 1670,1180 1770,1180 1770,1340 1830,1348.98 1830,1390 1684.56,1390
AGND on Top Layer "TOP_LAYER_AGND_P010" (solid, remove dead copper, pour order 10): 1130,1110 1130,1020 1571.23,1020 1571.23,890 1840,890 1840,1030 1840,1070 1940,1070 1940,1270 1940,1410 1940,1560 2070,1660 2070,1740 1850,1740 1850,1340 1610,1260 1560,1110
DGND on Top Layer "TOP_LAYER_DGND_P012" (solid, remove dead copper, pour order 12): 1840,850.18 1840,560 1840,276.01 1723.29,159.3 1132.79,160 499,866 260,866 260,940 360,940 360,1070 360,1499 574.49,1290 1290,1290 1610,850.18
5V on Top Layer "TOP_LAYER_5V_P022" (solid, remove dead copper, pour order 22): 350,960 350,1720 265,1720 265,960
DGND on Bottom Layer "BOTTOM_LAYER_DGND_P020" (solid, remove dead copper, pour order 20): 1840,840 1560,840 1560,1020 1110,1020 1060,1020 1060,1172.1 1060,1290 574.49,1290 290,1570 290,1600 52.5,1600 52.5,1510 160,1510 160,1070 360,1070 360,160 1840,160

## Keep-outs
Keep-Out Layer:
  text ".Layer_Name" at 577,-858.49 h60

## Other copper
Top Layer:
  text ".Layer_Name" at 577,-858.49 h60
Bottom Layer:
  text ".Layer_Name" at 577,-858.49 h60

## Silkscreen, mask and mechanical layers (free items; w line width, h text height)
Top Overlay:
  drawing of 161 lines, arcs and shapes, not listed
  text "Motor Supply" at 1754,1911 h55
  text "30V MAX" at 1800,1862 h50
  text "+" at 2027,1854 h60
  text "VIN" at 1913,1785 h50
  text "AGND" at 1855,1685 h50
  text "VCC" at 1762,1600 h23
  text "DGND" at 50,1502 h35
  text "CH1" at 427,1497 h40
  text "CH2" at 526,1497 h40
  text "CH3" at 625,1497 h40
  text "CH4" at 725,1497 h40
  text "VCC" at 822,1497 h40
  text "VCC" at 923,1497 h40
  text "CH5" at 1106,1497 h40
  text "CH6" at 1206,1497 h40
  text "CH7" at 1306,1497 h40
  text "CH8" at 1405,1497 h40
  text "VCC" at 1503,1497 h40
  text "VCC" at 1603,1497 h40
  text "Motor 1" at 556,1419 h110
  text "Motor 2" at 1230,1419 h110
  text "Motor 2" at 1230,1419 h110
  text "Diode / Bypass" at 1841,1380 h35
  text "3 GPIO / Dual Stepper Motor Driver" at 1040,1354 h23
  text "Flyback / COM Diode" at 1769,1261 h35
  text "Motor 1 Control Signals" at 470,1230 h23
  text "IN1" at 515,1190 h23
  text "IN2" at 630,1190 h23
  text "IN3" at 750,1190 h23
  text "IN4" at 870,1190 h23
  text "5V" at 325.5,1112.5 h72.83 r90
  text "3V3" at 224,1098 h72.83 r90
  text "LED / ENABLE" at 350,1080 h23
  text "VDD" at 1950,1042 h35
  text "AGND" at 1690,990 h23
  text "ULN2003A" at 1230,980 h29 r90
  text "40" at 1852,943 h35
  text "VDD" at 150,942 h35
  text "DGND" at 1950,942 h35
  text "*GP2" at 50,901.58 h35
  text "J5" at 80,866 h45
  text "*GP2" at 150,842 h35
  text "DGND" at 248,842 h35
  text "IN1" at 1226,824 h20 r90
  text "IN2" at 1275,824 h20 r90
  text "IN3" at 1325,824 h20 r90
  text "IN4" at 1375,823 h20 r90
  text "IN5" at 1425,823 h20 r90
  text "IN6" at 1475,823 h20 r90
  text "IN7" at 1525,823 h20 r90
  text "IN8" at 1575,823 h20 r90
  text "DGND" at 1690,750 h23
  text "*GP6" at 50,642 h35
  text "SN74HC595" at 1130,560 h29 r90
  text "*GP8" at 50,542 h35
  text "Switch" at 1449,460 h72.83
  text "Mode" at 1677,460 h72.83
  text "*GP6" at 150,442 h35
  text "IN1" at 410,435 h29
  text "IN2" at 705,435 h29
  text "IN3" at 920,435 h29
  text "BYPASS" at 1232,435 h29
  text "8-pin" at 1682,389 h72.83
  text "GP11" at 385,365 h29
  text "GP12" at 705,365 h29
  text "GP13" at 895,365 h29
  text "HC595" at 1232,365 h29
  text "*GP9" at 50,341.74 h35
  text "3-pin" at 1682,310 h72.83
  text "SER" at 400,297 h29
  text "RCLK" at 705,295 h29
  text "SRCLK" at 860,295 h29
  text "ENABLE" at 1232,293 h29
  text "*GP10" at 50.16,242 h35
  text "*GP8" at 150,242 h35
  text "GP13" at 1950,242 h35
  text "BOOSTXL-ULN2003" at 1160,165 h45
  text "*GP9" at 150,142 h35
  text "GP12" at 1950,142 h35
  text "'.PRJ_Number'.PCB_Rev" at 1460,95 h40
  text "*GP10" at 150,41 h35
  text ".Layer_Name" at 577,-858.49 h60
Bottom Overlay:
  drawing of 3623 lines, arcs and shapes, not listed
  text "CH1" at 495,1915 h40
  text "CH2" at 593,1915 h40
  text "CH3" at 691,1915 h40
  text "CH4" at 790,1915 h40
  text "VCC" at 893,1915 h40
  text "VCC" at 996,1915 h40
  text "CH5" at 1177,1915 h40
  text "CH6" at 1275,1915 h40
  text "CH7" at 1373,1915 h40
  text "CH8" at 1471,1915 h40
  text "VCC" at 1574,1915 h40
  text "VCC" at 1677,1915 h40
  text "Motor Supply" at 2040,1910 h55
  text "30V MAX" at 1986,1862 h50
  text "+" at 2027,1854 h60
  text "Motor 1" at 864,1823 h110
  text "Motor 2" at 1551,1820 h110
  text "VIN" at 1984,1785 h50
  text "J9" at 1987,1736 h45
  text "AGND" at 1984,1685 h50
  text "J7" at 414,1585 h45 r90
  text "J8" at 1095,1582 h45 r90
  text "J6" at 2023,1545 h45
  text "DGND" at 14,1510 h35 r270
  text "VDD" at 2081,1131 h35 r90
  text "DGND" at 2082,1038 h35 r90
  text "40" at 1808,981 h45 r270
  text "J5" at 122,866 h45
  text "Dual Stepper Motor Driver BoosterPack" at 1620,550 h72.83
  text "BOOSTXL-ULN2003" at 1625,474.22 h72.83
  text "Rev 1.0" at 1625,406.36 h60
  text "GP13" at 2082,339 h35 r90
  text "GP12" at 2082,237 h35 r90
  text "GP11" at 2082,137 h35 r90
  text "30" at 390,120 h45 r90
  text "31" at 1812,82 h45 r270
  text "J0" at 121,7 h45
  text "J1" at 220,7 h45
  text "J3" at 321,7 h45
  text "J4" at 1921,7 h45
  text "J2" at 2021,7 h45
  text ".Layer_Name" at 577,-858.49 h60
Top Paste:
  text ".Layer_Name" at 577,-858.49 h60
Bottom Paste:
  text ".Layer_Name" at 577,-858.49 h60
Top Solder:
  text ".Layer_Name" at 577,-858.49 h60
  text ".Layer_Name" at 577,-858.49 h60
Bottom Solder:
  text ".Layer_Name" at 577,-858.49 h60
Drill Guide:
  text ".Layer_Name" at 577,-858.49 h60
M1 Board Outline:
  the board outline again, w10
  text ".Layer_Name" at 577,-858.49 h60
M2 Board Dimensions:
  rectangle: 0,-275 125,-150
  rectangle: 125,-400 500,-275
  lines w7: 0,-275 1000,-275 ; 125,-400 125,-150 ; 250,-400 250,-150 ; 500,-400 500,-150 ; 750,-400 750,-150 ; 0,-400 1000,-400 1000,-150 0,-150 0,-400
  text ".Layer_Name" at 577,-858.49 h60
M3 3D STEP Top:
  text ".Layer_Name" at 577,-858.49 h60
M4 3D STEP Bottom:
  text ".Layer_Name" at 577,-858.49 h60
M5 Assembly Top:
  lines w10: -292,-930.17 6308,-930.17 ; -292,-726.83 6310,-726.83 ; -292,-523.5 -292,-1133.5 3713,-1133.5 6310,-1133.5 6310,-523.5 -291.5,-523.5 -291.5,-1133.5 1284,-1133.5 ; 2173,-1133.5 2173,-523.5 ; 3440,-726.83 3440,-523.5 ; 4280,-726.83 4280,-523.5 ; 4902,-1140 4902,-937.17
  text "COMPONENTS MARKED 'DNP' SHOULD NOT BE POPULATED." at 1153.5,-318.5 h60
  text "ASSEMBLY VARIANT:" at 1153,-434 h60
  text ".VariantName" at 2189,-434 h60
  text "PCB VIEWED FROM TOP SIDE" at -228.5,-655.67 h60
  text "BOARD #:" at 2248,-655.67 h60
  text ".PRJ_Number" at 2793.5,-655.67 h60
  text "REV:" at 3638,-655.67 h60
  text ".PCB_Rev" at 3929.5,-655.67 h60
  text "SVN REV:" at 4476,-655.67 h60
  text ".VersionControl_RevNumber" at 4982,-655.67 h60
  text "TID #:" at 2248,-859 h60
  text ".TID" at 2793.5,-859 h60
  text "PLOT NAME =" at -228.5,-1064.34 h60
  text ".plot_File_Name" at 577,-1064.34 h60
  text "GENERATED    :" at 2250,-1064.34 h60
  text ".Print_Date" at 3119.5,-1064.34 h60
  text ".Print_Time" at 3848.5,-1064.34 h60
  text "TEXAS INSTRUMENTS" at 5113,-1064.34 h60
M6 Assembly Bottom:
  lines w10: -292.5,-727.33 6309.5,-727.33 ; -290.5,-930.67 6309.5,-930.67 ; 1115.5,-1140.5 1115.5,-937.67 ; 1737.5,-727.33 1737.5,-524 ; 2577.5,-727.33 2577.5,-524 ; 3844.5,-1134 3844.5,-524 ; 4733.5,-1134 6309,-1134 6309,-524 -292.5,-524 -292.5,-1134 2304.5,-1134 6309.5,-1134 6309.5,-524
  text "COMPONENTS MARKED 'DNP' SHOULD NOT BE POPULATED." at 6102,-318 h60
  text ".VariantName" at 5058,-434 h60
  text "ASSEMBLY VARIANT:" at 6097,-434 h60
  text ".VersionControl_RevNumber" at 1035.5,-656.17 h60
  text "SVN REV:" at 1541.5,-656.17 h60
  text ".PCB_Rev" at 2088,-656.17 h60
  text "REV:" at 2379.5,-656.17 h60
  text ".PRJ_Number" at 3224,-656.17 h60
  text "BOARD #:" at 3769.5,-656.17 h60
  text "PCB VIEWED FROM BOTTOM SIDE" at 6246,-656.17 h60
  text ".TID" at 3224,-859.5 h60
  text "TID #:" at 3769.5,-859.5 h60
  text "TEXAS INSTRUMENTS" at 904.5,-1064.84 h60
  text ".Print_Time" at 2169,-1064.84 h60
  text ".Print_Date" at 2898,-1064.84 h60
  text "GENERATED    :" at 3767.5,-1064.84 h60
  text ".plot_File_Name" at 5440.5,-1064.84 h60
  text "PLOT NAME =" at 6246,-1064.84 h60
M9 Title Sheet:
  drawing of 57 lines, arcs and shapes, not listed
  text "1" at 739.84,8036.5 h70
  text "2" at 3235.5,8036.5 h70
  text "3" at 5724.84,8036.5 h70
  text "4" at 8231.51,8036.5 h70
  text "5" at 10730.5,8036.5 h70
  text "6" at 13235.5,8036.5 h70
  text "A" at -416.5,6893.5 h70
  text "A" at 14383.5,6893.5 h70
  text "B" at -416.5,4513.5 h70
  text "B" at 14383.5,4513.5 h70
  text "C" at -416.5,2138.5 h70
  text "C" at 14383.5,2138.5 h70
  text "PROJECT TITLE:" at 11343.5,277.5 h45
  text ".PRJ_Title" at 11393.5,144.17 h70
  text "DESIGNED FOR:" at 11343.5,-23.5 h45
  text ".PRJ_Customer" at 11393.5,-163.5 h70
  text "D" at -416.5,-231.5 h70
  text "D" at 14383.5,-231.5 h70
  text "FILE NAME:" at 11343.5,-323.5 h45
  text ".PCB_File_Name_No_Path" at 11393.5,-443.5 h70
  text "Texas Instruments (TI) and/or its licensors do not warrant the accuracy or completeness of this specification" at 6374,-605.34 h45
  text "ENGINEER:" at 11343.5,-613.5 h45
  text "LAYOUT BY:" at 12848.5,-613.5 h45
  text "or any information contained therein. TI and/or its licensors do not warrant that this design will meet" at 6329.01,-718 h45
  text ".PRJ_Engineer" at 11393.5,-768.49 h70
  text ".PCB_Layout" at 12899,-768.49 h70
  text "the specifications, will be suitable for your application or fit for any particular purpose, or will operate in" at 6329.01,-830.67 h45
  text ".Layer_Name" at 577,-858.49 h60
  text "ALTIUM DESIGNER VERSION:" at 12848.5,-923.5 h45
  text "an implementation. TI and/or its licensors do not warrant that the design is production worthy. You should" at 6329.01,-943.33 h45
  text "completely validate and test your design implementation to confirm the system functionality for your application." at 6374,-1056 h45
  text ".print_Scale" at 11393.5,-1056.83 h70
  text ".Application_BuildNumber" at 12899,-1056.83 h70
  text "1" at 739.84,-1263.5 h70
  text "2" at 3235.5,-1263.5 h70
  text "3" at 5724.84,-1263.5 h70
  text "4" at 8231.51,-1263.5 h70
  text "5" at 10730.5,-1263.5 h70
  text "6" at 13235.5,-1263.5 h70
M10 Fab Notes:
  drawing of 173 lines, arcs and shapes, not listed
  text "DESIGN INFORMATION" at 12378.02,6201 h60
  text "MIN. TRACK WIDTH:" at 11733.46,6021 h60
  text "8" at 12829.7,6021 h60
  text "MIL" at 12984.46,6021 h60
  text "MIN. CLEARANCE:" at 11733.46,5889 h60
  text "0.2" at 12769.7,5889 h60
  text "mm" at 12984.46,5889 h60
  text "MIN. VIA PAD SIZE:" at 11733.46,5757 h60
  text "24" at 12799.71,5757 h60
  text "MIL" at 12984.46,5757 h60
  text "0.05mm (2MIL)" at 12428.46,5615.29 h60
  text "MINIMUM ANNULAR RING" at 11404.23,5611 h60
  text "EXTERNAL" at 13136.46,5611 h60
  text "PER" at 11604.23,5493 h60
  text "IPC-D-275 CLASS 2 LEVEL C" at 11824.23,5493 h60
  text "MIL, HOLES" at 13312.46,5380.71 h60
  text "+/-" at 12920,5380 h60
  text "+/-" at 13774,5380 h60
  text "REGISTRATION TOLERANCES:" at 11404.23,5375 h60
  text "METAL" at 12604,5375 h60
  text "5" at 13180.2,5375 h60
  text "3" at 14013.2,5375 h60
  text "MIL" at 14129.46,5375 h60
  text "+/-" at 13774,5262 h60
  text "HOLE SIZE TOLERANCE (UNLESS OTHERWISE SPECIFIED):" at 11404.23,5257 h60
  text "3" at 14013.2,5257 h60
  text "MIL" at 14129.46,5257 h60
  text "MATERIAL:" at 11329.46,5047.54 h60
  text "FR-4 High Tg" at 12315.9,4907.21 h60
  text "FR-408" at 11750.46,4898.64 h60
  text "OTHER" at 13238.46,4898.64 h60
  text "X" at 12161,4895 h60
  text "62 MIL (1.6mm) +/-10%" at 12070.56,4735.92 h60
  text "THICKNESS:" at 11404.23,4731.64 h60
  text "X" at 11942.4,4731.64 h60
  text "OTHER" at 13355.46,4731.64 h60
  text "TOLERANCE:" at 11404.23,4573.64 h60
  text "X" at 12243.53,4573.64 h60
  text "ANSI IPC-6012 TYPE 3 CLASS 2" at 12430.48,4573.64 h60
  text "OTHER +/-" at 12430.46,4417.64 h60
  text "BOW & TWIST:" at 11404.23,4260.64 h60
  text "X" at 12243.53,4260.64 h60
  text "ANSI IPC-6012 TYPE 3 CLASS 2" at 12430.48,4260.64 h60
  text "OTHER +/-" at 12430.46,4102.13 h60
  text "DRILLING:" at 11329.46,3963.64 h60
  text "REFERENCE:" at 11404.23,3846.64 h60
  text "X" at 12052.46,3846.64 h60
  text "AS SHOWN" at 12239.46,3846.64 h60
  text "X" at 12953.46,3846.64 h60
  text "NC_DRILL FILES" at 13090.46,3846.64 h60
  text "PTH COPPER THICKNESS:" at 11404.23,3688.64 h60
  text "X" at 12534.46,3688.64 h60
  text "20-30 um" at 12671.46,3688.64 h60
  text "OTHER" at 13388.46,3688.64 h60
  text "BOARD FINISH:" at 11329.46,3529.64 h60
  text "SILKSCREEN:" at 11484.68,3411.64 h60
  text "X" at 12433.46,3411.64 h60
  text "TOP" at 12559.46,3411.64 h60
  text "X" at 12943.46,3411.64 h60
  text "BOTTOM" at 13070.46,3411.64 h60
  text "SILKSCREEN COLOR:" at 11484.68,3244.64 h60
  text "X" at 12432.42,3244.64 h60
  text "WHITE" at 12559.46,3244.64 h60
  text "OTHER" at 13070.46,3244.64 h60
  text "GREEN" at 12690.46,3085.44 h60
  text "OTHER" at 13308.46,3085.44 h60
  text "X" at 13150,3080 h60
  text "SOLDER RESIST COLOR:" at 11484.68,3074.64 h60
  text "RED" at 13798.46,3075.44 h60
  text "X" at 12563.42,2915.44 h60
  text "MATTE" at 12690.46,2915.44 h60
  text "SEMI-GLOSS" at 13308,2914.8 h60
  text "IMMERSION GOLD (ENIG)" at 12390.46,2726.92 h60
  text "ENEPIG" at 13728,2723.64 h60
  text "SURFACE FINISH:" at 11329.46,2722.64 h60
  text "X" at 12203.51,2722.64 h60
  text "IMM. TIN/SILVER OR EQUIV" at 11659,2565.64 h60
  text "OTHER" at 13090.46,2565.64 h60
  text "ARRAY/PANEL:" at 11329.46,2386.64 h60
  text "CUT AND TRIM PER M1 BOARD OUTLINE" at 12390.46,2382.35 h60
  text "N.C. ROUTE" at 12390.46,2230.64 h60
  text "X" at 13069.46,2230.64 h60
  text "V. SCORE" at 13256.46,2230.64 h60
  text "CERTIFICATION:" at 11329.46,2093.64 h60
  text "MATERIALS AND WORKMANSHIP FOR ALL PCBS" at 12054.46,2093.64 h60
  text "TO MEET OR EXCEED THE REQUIREMENTS OF:" at 12054.46,1995.64 h60
  text "X" at 11680.96,1859.13 h60
  text "ANSI IPC-A-600F CLASS ->" at 11819.96,1859.13 h60
  text "X" at 13459.02,1859.13 h60
  text "2" at 13577.96,1859.14 h60
  text "1" at 13262.96,1857.64 h60
  text "3" at 13931.96,1857.64 h60
  text "X" at 12495.02,1699.64 h60
  text "RoHS" at 12631.96,1699.64 h60
  text "OTHER" at 13276.36,1699.64 h60
  text "PER ORDER" at 13673.42,1699.64 h60
  text "ALL BOARDS MUST MEET OR EXCEED UL94-V0 REQUIREMENTS." at 11357,1534 h60
  text "PCB MUST BEAR THE UL94V-0 UL REGISTERED MATERIAL ID NUMBER" at 11357,1414 h60
  text "ADDITIONAL REQUIREMENTS:" at 11329.46,1240.64 h60
  text "MICROSECTION:" at 11404.23,1125.64 h60
  text "YES" at 12309.96,1125.64 h60
  text "REQUIRED" at 13171.46,969.49 h60
  text "BARE BOARD ELEC. TEST:" at 11404.23,966.64 h60
  text "NONE" at 12709.96,966.64 h60
  text "X" at 13044.46,966.64 h60
  text "PER ORDER" at 13763.46,966.64 h60
  text ".Layer_Name" at 577,-858.49 h60
M11 Gerber Information:
  lines w10: -292,-930.17 6308,-930.17 ; -292,-726.83 6310,-726.83 ; -292,-523.5 -292,-1133.5 3713,-1133.5 6310,-1133.5 6310,-523.5 -291.5,-523.5 -291.5,-1133.5 1284,-1133.5 ; 2173,-1133.5 2173,-523.5 ; 3440,-726.83 3440,-523.5 ; 4280,-726.83 4280,-523.5 ; 4902,-1140 4902,-937.17
  text "ALL ARTWORK VIEWED FROM TOP SIDE" at -228.5,-655.67 h60
  text "BOARD #:" at 2248,-655.67 h60
  text ".PRJ_Number" at 2793.5,-655.67 h60
  text "REV:" at 3638,-655.67 h60
  text ".PCB_Rev" at 3929.5,-655.67 h60
  text "SVN REV:" at 4476,-655.67 h60
  text ".VersionControl_RevNumber" at 4982,-655.67 h60
  text "LAYER NAME =" at -228.5,-858.49 h60
  text "TID #:" at 2248,-859 h60
  text ".TID" at 2793.5,-859 h60
  text "PLOT NAME =" at -228.5,-1064.34 h60
  text ".plot_File_Name" at 577,-1064.34 h60
  text "GENERATED    :" at 2250,-1064.34 h60
  text ".Print_Date" at 3119.5,-1064.34 h60
  text ".Print_Time" at 3848.5,-1064.34 h60
  text "TEXAS INSTRUMENTS" at 5113,-1064.34 h60
M12 Stackup:
  drawing of 191 lines, arcs and shapes, not listed
  text "Layer" at 9790.34,7830 h60
  text "Name" at 10200.26,7830 h60
  text "Material" at 11130,7830 h60
  text "Thickness" at 11989.77,7830 h60
  text "Constant" at 12639.6,7830 h60
  text "Board Layer Stack" at 13209.46,7830 h60
  text "1" at 9790.34,7710 h60
  text "Top Overlay" at 10200.26,7710 h60
  text "2" at 9790.34,7590 h60
  text "Top Solder" at 10200.26,7590 h60
  text "Solder Resist" at 11130,7590 h60
  text "0.40mil" at 11989.77,7590 h60
  text "3.5" at 12639.6,7590 h60
  text "3" at 9790.34,7470 h60
  text "Top Layer" at 10200.26,7470 h60
  text "Copper" at 11130,7470 h60
  text "1.40mil" at 11989.77,7470 h60
  text "4" at 9790.34,7350 h60
  text "Dielectric1" at 10200.26,7350 h60
  text "FR-4" at 11130,7350 h60
  text "59.20mil" at 11989.77,7350 h60
  text "4.8" at 12639.6,7350 h60
  text "5" at 9790.34,7230 h60
  text "Bottom Layer" at 10200.26,7230 h60
  text "Copper" at 11130,7230 h60
  text "1.40mil" at 11989.77,7230 h60
  text "6" at 9790.34,7110 h60
  text "Bottom Solder" at 10200.26,7110 h60
  text "Solder Resist" at 11130,7110 h60
  text "0.40mil" at 11989.77,7110 h60
  text "3.5" at 12639.6,7110 h60
  text "7" at 9790.34,6990 h60
  text "Bottom Overlay" at 10200.26,6990 h60
  text ".Layer_Name" at 577,-858.49 h60
M13 Component Bodies Top:
  text ".Layer_Name" at 577,-858.49 h60
M14 Component Bodies Bottom:
  text ".Layer_Name" at 577,-858.49 h60
M15 Courtyards Top:
  text ".Layer_Name" at 577,-858.49 h60
M16 Courtyards Bottom:
  text ".Layer_Name" at 577,-858.49 h60
Drill Drawing:
  lines w10: 5336.14,2865.04 5391.46,2865.04 5391.46,2920.36 5336.14,2920.36 5336.14,2865.04 ; 5336.14,2989.5 5363.8,3003.33 5391.46,2989.5 5377.63,3017.16 5391.46,3044.82 5363.8,3030.99 5336.14,3044.82 5349.97,3017.16 5336.14,2989.5 ; 5336.14,3169.28 5391.46,3169.28 5363.8,3113.96 5336.14,3169.28 ; 5336.14,3238.42 5336.14,3252.25 5349.97,3266.08 5336.14,3279.91 5336.14,3293.74 5349.97,3293.74 5363.8,3279.91 5377.63,3293.74 5391.46,3293.74 5391.46,3279.91 5377.63,3266.08 5391.46,3252.25 5391.46,3238.42 5377.63,3238.42 5363.8,3252.25 5349.97,3238.42 5336.14,3238.42
  lines w12: 5286,2827.71 8518.76,2827.71 ; 5286,3325.54 8518.76,3325.54 ; 5624.17,2703.25 5624.17,3450 ; 5956.28,2703.25 5956.28,3450 ; 6593.29,2703.25 6593.29,3450 ; 6852.64,2703.25 6852.64,3450 ; 7228.06,2703.25 7228.06,3450 ; 7951.91,2703.25 7951.91,3450 ; 5286,2703.25 8518.76,2703.25 8518.76,3450 5286,3450 5286,2703.25
  text "Symbol" at 5360.68,3362.88 h72
  text "Quantity" at 5661.51,3362.88 h72
  text "Finished Hole Size" at 5993.62,3362.88 h72
  text "Plated" at 6630.62,3362.88 h72
  text "Hole Type" at 6889.98,3362.88 h72
  text "Drill Layer Pair" at 7265.4,3362.88 h72
  text "Hole Tolerance" at 7989.25,3362.88 h72
  text "34" at 5661.51,3238.42 h60
  text "10.00mil (0.254mm)" at 5993.62,3238.42 h60
  text "PTH" at 6630.62,3238.42 h60
  text "Round" at 6889.98,3238.42 h60
  text "Top Layer - Bottom Layer" at 7265.4,3238.42 h60
  text "13" at 5661.51,3113.96 h60
  text "40.00mil (1.016mm)" at 5993.62,3113.96 h60
  text "PTH" at 6630.62,3113.96 h60
  text "Round" at 6889.98,3113.96 h60
  text "Top Layer - Bottom Layer" at 7265.4,3113.96 h60
  text "62" at 5661.51,2989.5 h60
  text "40.16mil (1.020mm)" at 5993.62,2989.5 h60
  text "PTH" at 6630.62,2989.5 h60
  text "Round" at 6889.98,2989.5 h60
  text "Top Layer - Bottom Layer" at 7265.4,2989.5 h60
  text "2" at 5661.51,2865.04 h60
  text "48.00mil (1.219mm)" at 5993.62,2865.04 h60
  text "PTH" at 6630.62,2865.04 h60
  text "Round" at 6889.98,2865.04 h60
  text "Top Layer - Bottom Layer" at 7265.4,2865.04 h60
  text "111 Total" at 5661.51,2740.59 h60
  text ".Layer_Name" at 577,-858.49 h60
M17 Embedded Cavity:
  text ".Layer_Name" at 577,-858.49 h60
M18 Embedded Assembly:
  text ".Layer_Name" at 577,-858.49 h60
M19 Embedded Keepout:
  text ".Layer_Name" at 577,-858.49 h60

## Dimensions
0,-400 to 1000,-400 on M2 Board Dimensions
0,0 to 0,1960 on M2 Board Dimensions
0,0 to 0,1960 on M2 Board Dimensions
